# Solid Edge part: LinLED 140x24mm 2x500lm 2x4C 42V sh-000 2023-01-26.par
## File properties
Author: jaroslaw.przewlocki
Template: iso metric part.par
Last saved by: jaroslaw.przewlocki
Revision: 1
Application: Solid Edge
Gęstość: 0,000 kg/m^3
Dokładność: 0,990
Username: jaroslaw.przewlocki
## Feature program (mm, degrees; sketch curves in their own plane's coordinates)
body "unnamed Body 1"
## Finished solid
Body 1: solid body, 2368 faces, 6008 edges, 3772 vertices.
  Faces by surface: plane 1212, cylinder 532, torus 256, cone 200, spline 104, sphere 64
  Edges by curve: line 3552, curve on surface 1424, circle 624, ellipse 264, spline 144
Bounding box of the edges (mm; curved faces can reach further): 139.600 x 24.000 x 4.450, from (-69.8, -12, -1) to (69.8, 12, 3.45).
Cylindrical faces by radius (mm): R0.2 x184, R0.2169 x24, R0.25 x56, R0.3373 x24, R0.4 x32, R0.4006 x8, R0.4008 x8, R0.525 x8, R0.6 x80, R1 x32, R1.1 x16, R1.1989 x8, R1.199 x8, R1.2 x40, R2.15 x4
Conical faces (half-angle, radius in mm at the cone's reference point): 0.398 deg R1.1964 x8, 0.4493 deg R1.1964 x8, 0.4746 deg R1.1948 x8, 0.4758 deg R1.1948 x8, 0.5 deg R0.5056 x16, 0.5 deg R1.0082 x16, 1 deg R0.5511 x8, 10 deg R0.2132 x16, 10 deg R0.4132 x16, 16.0099 deg R1.1053 x8, 16.1249 deg R1.1279 x8, 18.8604 deg R1.0669 x16, 19.5041 deg R0.5138 x8, 19.8244 deg R0.5099 x8, 27.363 deg R0.6214 x8, 40.6434 deg R0.5161 x8, 43.3309 deg R0.4892 x8, 45 deg R0.575 x8, 45 deg R0.625 x16
Toroidal faces (ring radius, tube radius in mm): R0.0958 r0.3997 x16, R0.1076 r0.4 x8, R0.1101 r0.4001 x8, R0.1217 r0.4 x8, R0.1234 r0.4 x8, R0.1626 r0.228 x8, R0.1634 r0.2287 x8, R0.3287 r0.2001 x8, R0.3684 r0.2151 x8, R0.3703 r0.4 x8, R0.3818 r0.2 x16, R0.4166 r0.3983 x8, R0.5981 r0.197 x8, R0.5982 r0.197 x8, R0.6009 r0.3968 x8, R0.6009 r0.3969 x8, R0.6227 r0.2 x8, R0.6235 r0.2 x8, R0.8 r0.2 x16, R0.8522 r0.3 x8, R0.9002 r0.2 x8, R0.9018 r0.2 x8, R0.9197 r0.223 x8, R0.9365 r0.2 x8, R0.9663 r0.2263 x8, R0.9665 r0.2263 x8, R1.429 r1.2 x8, R1.8741 r0.2175 x8, R1.9007 r0.2 x8
Spherical faces by radius (mm): R0.2 x48, R0.6 x16
Planar faces by outward normal: +x 119, +y 123, +z 181, -x 119, -y 125, -z 33, oblique 512
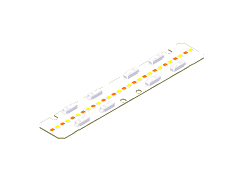
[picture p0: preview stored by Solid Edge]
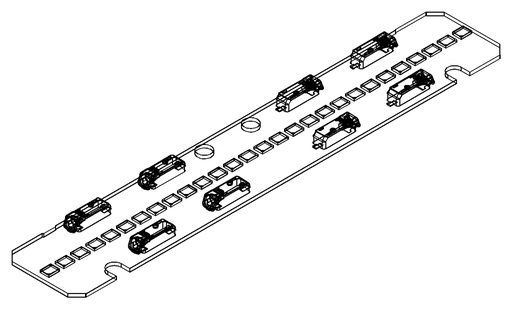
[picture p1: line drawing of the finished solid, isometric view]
